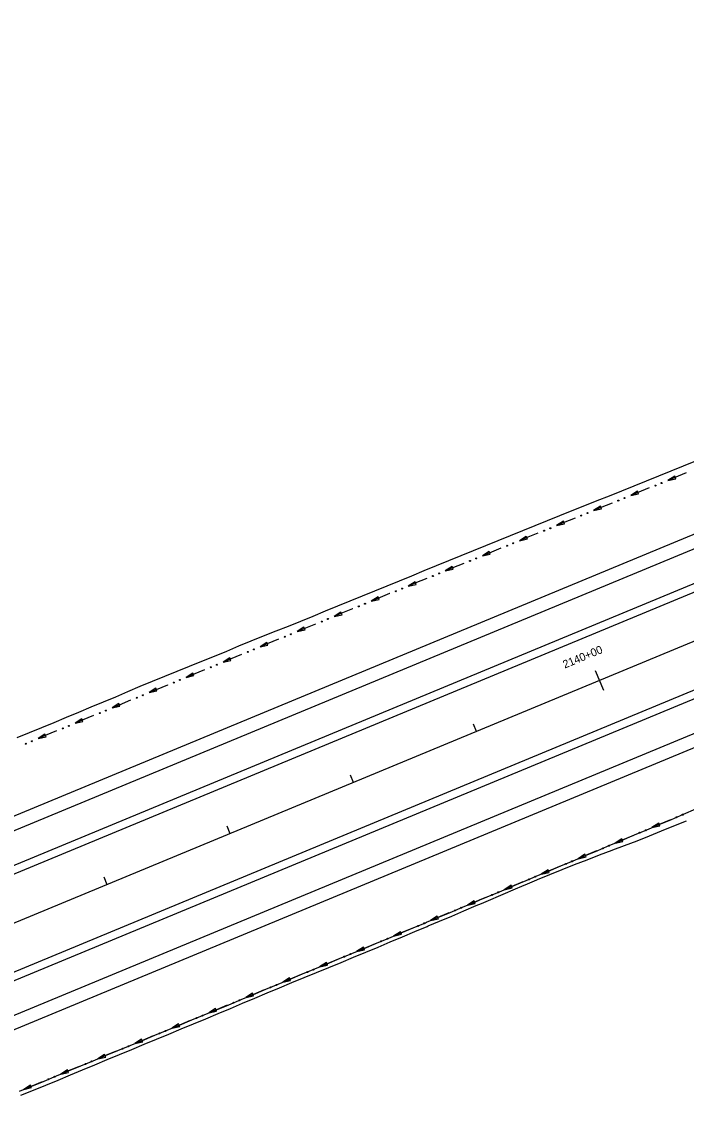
# Model space of a CAD drawing. Extents: x 1611108 to 1749517, y 619561 to 797725.
# Drawn here: x 1719500 to 1719999, y 767079 to 767893 of the extents above; entities that cross this region are included whole.
import ezdxf

# ---------------------------------------------------------------- set-up
doc = ezdxf.new("R2010")
doc.units = 0
for name, color, linetype in [('R_Ditch', 7, 'Continuous'), ('R_Horz Alg', 7, 'Continuous'), ('R_Horz Alg Stationing', 7, 'Continuous'), ('R_Proposed Const Limits', 7, 'Continuous'), ('R_Proposed Road', 7, 'Continuous')]:
    doc.layers.add(name, color=color, linetype=linetype)

msp = doc.modelspace()

# ---------------------------------------------------------------- linework, layer by layer
at = {"layer": 'R_Ditch'}
for p, q in [((1719990.05, 767551.97), (1719984.89, 767548.74)), ((1719990.85, 767550.01), (1719990.05, 767551.97)), ((1719984.89, 767548.74), (1719990.85, 767550.01)), ((1719962.21, 767540.7), (1719957.04, 767537.47)), ((1719957.04, 767537.47), (1719963, 767538.74)), ((1719963, 767538.74), (1719962.21, 767540.7)), ((1719934.37, 767529.42), (1719929.2, 767526.19)), ((1719929.2, 767526.19), (1719935.16, 767527.46)), ((1719935.16, 767527.46), (1719934.37, 767529.42)), ((1719906.53, 767518.13), (1719901.37, 767514.89)), ((1719907.33, 767516.17), (1719906.53, 767518.13)), ((1719901.37, 767514.89), (1719907.33, 767516.17)), ((1719878.7, 767506.82), (1719873.54, 767503.58)), ((1719873.54, 767503.58), (1719879.5, 767504.86)), ((1719879.5, 767504.86), (1719878.7, 767506.82)), ((1719850.88, 767495.5), (1719845.72, 767492.25)), ((1719851.68, 767493.54), (1719850.88, 767495.5)), ((1719845.72, 767492.25), (1719851.68, 767493.54)), ((1719823.07, 767484.16), (1719817.91, 767480.91)), ((1719817.91, 767480.91), (1719823.86, 767482.2)), ((1719823.86, 767482.2), (1719823.07, 767484.16)), ((1719795.26, 767472.8), (1719790.1, 767469.55)), ((1719790.1, 767469.55), (1719796.06, 767470.84)), ((1719796.06, 767470.84), (1719795.26, 767472.8)), ((1719767.45, 767461.43), (1719762.3, 767458.18)), ((1719768.25, 767459.48), (1719767.45, 767461.43)), ((1719762.3, 767458.18), (1719768.25, 767459.48)), ((1719739.65, 767450.05), (1719734.5, 767446.8)), ((1719734.5, 767446.8), (1719740.46, 767448.09)), ((1719740.46, 767448.09), (1719739.65, 767450.05)), ((1719711.86, 767438.65), (1719706.71, 767435.39)), ((1719706.71, 767435.39), (1719712.67, 767436.69)), ((1719712.67, 767436.69), (1719711.86, 767438.65)), ((1719684.08, 767427.24), (1719678.93, 767423.98)), ((1719678.93, 767423.98), (1719684.88, 767425.28)), ((1719684.88, 767425.28), (1719684.08, 767427.24)), ((1719656.3, 767415.81), (1719651.15, 767412.54)), ((1719651.15, 767412.54), (1719657.1, 767413.85)), ((1719657.1, 767413.85), (1719656.3, 767415.81)), ((1719628.52, 767404.36), (1719623.38, 767401.1)), ((1719629.33, 767402.41), (1719628.52, 767404.36)), ((1719623.38, 767401.1), (1719629.33, 767402.41)), ((1719600.76, 767392.9), (1719595.62, 767389.63)), ((1719595.62, 767389.63), (1719601.57, 767390.95)), ((1719601.57, 767390.95), (1719600.76, 767392.9)), ((1719573, 767381.43), (1719567.86, 767378.16)), ((1719573.81, 767379.47), (1719573, 767381.43)), ((1719567.86, 767378.16), (1719573.81, 767379.47)), ((1719545.24, 767369.94), (1719540.1, 767366.67)), ((1719540.1, 767366.67), (1719546.05, 767367.99)), ((1719546.05, 767367.99), (1719545.24, 767369.94)), ((1719517.49, 767358.44), (1719512.36, 767355.16)), ((1719512.36, 767355.16), (1719518.31, 767356.48)), ((1719518.31, 767356.48), (1719517.49, 767358.44)), ((1719978.09, 767291.75), (1719972.98, 767288.45)), ((1719978.91, 767289.8), (1719978.09, 767291.75)), ((1719972.98, 767288.45), (1719978.91, 767289.8)), ((1719950.41, 767280.08), (1719945.3, 767276.78)), ((1719945.3, 767276.78), (1719951.24, 767278.13)), ((1719951.24, 767278.13), (1719950.41, 767280.08)), ((1719922.73, 767268.43), (1719917.61, 767265.13)), ((1719917.61, 767265.13), (1719923.55, 767266.48)), ((1719923.55, 767266.48), (1719922.73, 767268.43)), ((1719895.04, 767256.79), (1719889.92, 767253.49)), ((1719889.92, 767253.49), (1719895.86, 767254.84)), ((1719895.86, 767254.84), (1719895.04, 767256.79)), ((1719867.34, 767245.16), (1719862.22, 767241.87)), ((1719862.22, 767241.87), (1719868.16, 767243.21)), ((1719868.16, 767243.21), (1719867.34, 767245.16)), ((1719839.64, 767233.55), (1719834.52, 767230.26)), ((1719840.46, 767231.6), (1719839.64, 767233.55)), ((1719834.52, 767230.26), (1719840.46, 767231.6)), ((1719811.93, 767221.96), (1719806.8, 767218.67)), ((1719806.8, 767218.67), (1719812.75, 767220)), ((1719812.75, 767220), (1719811.93, 767221.96)), ((1719784.22, 767210.38), (1719779.09, 767207.09)), ((1719785.03, 767208.42), (1719784.22, 767210.38)), ((1719779.09, 767207.09), (1719785.03, 767208.42)), ((1719756.5, 767198.81), (1719751.36, 767195.53)), ((1719751.36, 767195.53), (1719757.31, 767196.86)), ((1719757.31, 767196.86), (1719756.5, 767198.81)), ((1719728.77, 767187.26), (1719723.63, 767183.98)), ((1719723.63, 767183.98), (1719729.58, 767185.31)), ((1719729.58, 767185.31), (1719728.77, 767187.26)), ((1719701.03, 767175.72), (1719695.9, 767172.45)), ((1719695.9, 767172.45), (1719701.85, 767173.77)), ((1719701.85, 767173.77), (1719701.03, 767175.72)), ((1719673.29, 767164.2), (1719668.16, 767160.93)), ((1719668.16, 767160.93), (1719674.1, 767162.25)), ((1719674.1, 767162.25), (1719673.29, 767164.2)), ((1719645.55, 767152.7), (1719640.41, 767149.43)), ((1719646.36, 767150.74), (1719645.55, 767152.7)), ((1719640.41, 767149.43), (1719646.36, 767150.74)), ((1719617.79, 767141.21), (1719612.65, 767137.94)), ((1719612.65, 767137.94), (1719618.6, 767139.25)), ((1719618.6, 767139.25), (1719617.79, 767141.21)), ((1719590.03, 767129.73), (1719584.89, 767126.46)), ((1719584.89, 767126.46), (1719590.84, 767127.78)), ((1719590.84, 767127.78), (1719590.03, 767129.73)), ((1719562.27, 767118.27), (1719557.13, 767115.01)), ((1719557.13, 767115.01), (1719563.08, 767116.32)), ((1719563.08, 767116.32), (1719562.27, 767118.27)), ((1719534.5, 767106.83), (1719529.35, 767103.56)), ((1719529.35, 767103.56), (1719535.3, 767104.87)), ((1719535.3, 767104.87), (1719534.5, 767106.83)), ((1719506.72, 767095.4), (1719501.57, 767092.14)), ((1719507.52, 767093.44), (1719506.72, 767095.4)), ((1719501.57, 767092.14), (1719507.52, 767093.44))]:
    msp.add_line(p, q, dxfattribs=at)
for points in [[(1719998.8, 767554.36), (1719989.73, 767550.69), (1719984.89, 767548.74)], [(1719970.95, 767543.1), (1719961.91, 767539.44), (1719957.04, 767537.47)], [(1719970.98, 767543.11), (1719970.95, 767543.1)], [(1719943.11, 767531.82), (1719934.11, 767528.18), (1719929.2, 767526.19)], [(1719943.14, 767531.84), (1719943.11, 767531.82)], [(1719915.27, 767520.54), (1719906.31, 767516.9), (1719901.37, 767514.89)], [(1719915.3, 767520.55), (1719915.27, 767520.54)], [(1719887.44, 767509.23), (1719878.52, 767505.6), (1719873.54, 767503.58)], [(1719887.47, 767509.25), (1719887.44, 767509.23)], [(1719859.62, 767497.91), (1719850.73, 767494.29), (1719845.72, 767492.25)], [(1719859.65, 767497.93), (1719859.62, 767497.91)], [(1719831.8, 767486.58), (1719822.95, 767482.97), (1719817.91, 767480.91)], [(1719831.83, 767486.59), (1719831.8, 767486.58)], [(1719803.99, 767475.23), (1719795.17, 767471.63), (1719790.1, 767469.55)], [(1719804.02, 767475.24), (1719803.99, 767475.23)], [(1719776.18, 767463.86), (1719767.41, 767460.27), (1719762.3, 767458.18)], [(1719776.22, 767463.88), (1719776.18, 767463.86)], [(1719748.38, 767452.48), (1719739.64, 767448.9), (1719734.5, 767446.8)], [(1719748.42, 767452.5), (1719748.38, 767452.48)], [(1719720.59, 767441.09), (1719711.89, 767437.52), (1719706.71, 767435.39)], [(1719720.63, 767441.1), (1719720.59, 767441.09)], [(1719692.8, 767429.68), (1719684.14, 767426.12), (1719678.93, 767423.98)], [(1719692.84, 767429.69), (1719692.8, 767429.68)], [(1719665.02, 767418.25), (1719656.39, 767414.7), (1719651.15, 767412.54)], [(1719665.06, 767418.27), (1719665.02, 767418.26)], [(1719637.25, 767406.82), (1719628.66, 767403.27), (1719623.38, 767401.1)], [(1719637.28, 767406.83), (1719637.25, 767406.82)], [(1719609.48, 767395.36), (1719600.93, 767391.83), (1719595.62, 767389.63)], [(1719609.52, 767395.38), (1719609.48, 767395.36)], [(1719581.72, 767383.89), (1719573.2, 767380.37), (1719567.86, 767378.16)], [(1719581.75, 767383.91), (1719581.72, 767383.89)], [(1719553.96, 767372.41), (1719545.48, 767368.89), (1719540.1, 767366.67)], [(1719554, 767372.42), (1719553.96, 767372.41)], [(1719526.21, 767360.91), (1719517.77, 767357.4), (1719512.36, 767355.16)], [(1719526.25, 767360.92), (1719526.21, 767360.91)], [(1719498.31, 767090.8), (1719507.56, 767094.6), (1719516.81, 767098.4), (1719526.06, 767102.21), (1719535.3, 767106.02), (1719544.55, 767109.82), (1719553.8, 767113.64), (1719563.04, 767117.45), (1719572.29, 767121.26), (1719581.53, 767125.08), (1719590.77, 767128.89), (1719600.02, 767132.71), (1719609.26, 767136.53), (1719618.5, 767140.35), (1719627.74, 767144.18), (1719636.98, 767148), (1719646.22, 767151.83), (1719655.45, 767155.66), (1719664.69, 767159.49), (1719673.93, 767163.32), (1719683.16, 767167.16), (1719692.4, 767170.99), (1719701.63, 767174.83), (1719710.87, 767178.67), (1719720.1, 767182.51), (1719729.33, 767186.35), (1719738.56, 767190.19), (1719747.79, 767194.04), (1719757.03, 767197.89), (1719766.26, 767201.73), (1719775.48, 767205.58), (1719784.71, 767209.44), (1719793.94, 767213.29), (1719803.17, 767217.15), (1719803.9, 767217.45), (1719812.39, 767221), (1719821.62, 767224.86), (1719830.84, 767228.72), (1719840.07, 767232.58), (1719843.87, 767234.18), (1719843.95, 767234.21), (1719849.29, 767236.45), (1719858.52, 767240.31), (1719862.08, 767241.81), (1719867.74, 767244.18), (1719876.14, 767247.7), (1719876.96, 767248.05), (1719885.63, 767251.69), (1719886.18, 767251.92), (1719895.4, 767255.79), (1719904.62, 767259.67), (1719913.84, 767263.54), (1719923.05, 767267.42), (1719932.27, 767271.3), (1719941.49, 767275.18), (1719942.18, 767275.47), (1719950.71, 767279.06), (1719959.92, 767282.94), (1719969.14, 767286.83), (1719978.35, 767290.71), (1719987.56, 767294.6), (1719996.78, 767298.49), (1720005.99, 767302.39)], [(1719986.8, 767294.28), (1719978.35, 767290.71), (1719972.98, 767288.45)], [(1719986.83, 767294.29), (1719986.8, 767294.28)], [(1719959.12, 767282.6), (1719950.71, 767279.06), (1719945.3, 767276.78)], [(1719959.15, 767282.62), (1719959.12, 767282.6)], [(1719931.44, 767270.94), (1719923.05, 767267.42), (1719917.61, 767265.13)], [(1719931.47, 767270.96), (1719931.44, 767270.94)], [(1719903.75, 767259.3), (1719895.4, 767255.79), (1719889.92, 767253.49)], [(1719903.78, 767259.31), (1719903.75, 767259.3)], [(1719876.05, 767247.67), (1719867.74, 767244.18), (1719862.22, 767241.87)], [(1719876.09, 767247.68), (1719876.05, 767247.67)], [(1719848.35, 767236.05), (1719843.95, 767234.21), (1719843.87, 767234.18), (1719840.07, 767232.58), (1719834.52, 767230.26)], [(1719848.39, 767236.07), (1719848.35, 767236.05)], [(1719820.64, 767224.45), (1719812.39, 767221), (1719806.8, 767218.67)], [(1719820.68, 767224.47), (1719820.64, 767224.45)], [(1719792.93, 767212.87), (1719784.71, 767209.44), (1719779.09, 767207.09)], [(1719792.96, 767212.88), (1719792.93, 767212.87)], [(1719765.21, 767201.3), (1719757.03, 767197.89), (1719751.36, 767195.53)], [(1719765.24, 767201.31), (1719765.21, 767201.3)], [(1719737.48, 767189.74), (1719729.33, 767186.35), (1719723.63, 767183.98)], [(1719737.52, 767189.76), (1719737.48, 767189.74)], [(1719709.75, 767178.2), (1719701.63, 767174.83), (1719695.9, 767172.45)], [(1719709.78, 767178.22), (1719709.75, 767178.2)], [(1719682.01, 767166.68), (1719673.93, 767163.32), (1719668.16, 767160.93)], [(1719682.05, 767166.69), (1719682.01, 767166.68)], [(1719654.27, 767155.17), (1719646.22, 767151.83), (1719640.41, 767149.43)], [(1719654.3, 767155.18), (1719654.27, 767155.17)], [(1719626.51, 767143.67), (1719618.5, 767140.35), (1719612.65, 767137.94)], [(1719626.55, 767143.69), (1719626.51, 767143.67)], [(1719598.76, 767132.19), (1719590.77, 767128.89), (1719584.89, 767126.46)], [(1719598.79, 767132.21), (1719598.76, 767132.19)], [(1719570.99, 767120.73), (1719563.04, 767117.45), (1719557.13, 767115.01)], [(1719571.03, 767120.74), (1719570.99, 767120.73)], [(1719543.22, 767109.28), (1719535.3, 767106.02), (1719529.35, 767103.56)], [(1719543.26, 767109.29), (1719543.22, 767109.28)], [(1719515.45, 767097.84), (1719507.56, 767094.6), (1719501.57, 767092.14)], [(1719515.48, 767097.86), (1719515.45, 767097.84)]]:
    msp.add_lwpolyline(points, dxfattribs=at)
for centre in [(1719975.62, 767544.95), (1719980.26, 767546.83), (1719952.42, 767535.56), (1719947.77, 767533.68), (1719919.94, 767522.39), (1719924.58, 767524.27), (1719892.11, 767511.09), (1719896.75, 767512.97), (1719868.92, 767501.66), (1719864.28, 767499.77), (1719836.46, 767488.44), (1719841.1, 767490.33), (1719808.65, 767477.09), (1719813.29, 767478.99), (1719780.84, 767465.73), (1719785.48, 767467.63), (1719753.04, 767454.35), (1719757.68, 767456.25), (1719729.89, 767444.86), (1719725.25, 767442.96), (1719697.46, 767431.55), (1719702.1, 767433.46), (1719669.68, 767420.13), (1719674.31, 767422.04), (1719641.91, 767408.7), (1719646.54, 767410.6), (1719614.14, 767397.24), (1719618.77, 767399.16), (1719591, 767387.69), (1719586.37, 767385.78), (1719558.62, 767374.29), (1719563.25, 767376.21), (1719535.49, 767364.72), (1719530.87, 767362.8), (1719503.12, 767351.28), (1719507.75, 767353.21), (1719996.05, 767298.15), (1719991.44, 767296.2), (1719963.76, 767284.52), (1719968.38, 767286.47), (1719940.7, 767274.8), (1719936.08, 767272.86), (1719908.39, 767261.21), (1719913.01, 767263.15), (1719880.7, 767249.58), (1719885.32, 767251.52), (1719853, 767237.96), (1719857.62, 767239.9), (1719825.29, 767226.36), (1719829.91, 767228.29), (1719802.2, 767216.7), (1719797.58, 767214.77), (1719769.86, 767203.2), (1719774.48, 767205.13), (1719746.76, 767193.57), (1719742.13, 767191.64), (1719714.4, 767180.1), (1719719.03, 767182.02), (1719686.66, 767168.57), (1719691.29, 767170.49), (1719658.92, 767157.06), (1719663.55, 767158.98), (1719631.17, 767145.56), (1719635.8, 767147.48), (1719608.04, 767135.99), (1719603.41, 767134.08), (1719575.65, 767122.61), (1719580.28, 767124.52), (1719547.88, 767111.16), (1719552.51, 767113.07), (1719520.1, 767099.72), (1719524.74, 767101.63)]:
    msp.add_circle(centre, 0.375, dxfattribs=at)
at = {"layer": 'R_Horz Alg'}
msp.add_line((1715964.86, 765755.05), (1723860.62, 769025.58), dxfattribs=at)
at = {"layer": 'R_Horz Alg Stationing'}
for points in [[(1719930.46, 767406.32), (1719936.59, 767391.54)], [(1719838.84, 767366.2), (1719841.14, 767360.66)], [(1719746.45, 767327.93), (1719748.75, 767322.39)], [(1719654.07, 767289.67), (1719656.36, 767284.12)], [(1719561.68, 767251.4), (1719563.97, 767245.85)]]:
    msp.add_lwpolyline(points, dxfattribs=at)
at = {"layer": 'R_Proposed Const Limits'}
for points in [[(1719496.7, 767356.01), (1719505.95, 767359.8), (1719515.25, 767363.49), (1719524.49, 767367.3), (1719533.7, 767371.21), (1719542.9, 767375.12), (1719552.14, 767378.94), (1719561.39, 767382.74), (1719570.63, 767386.58), (1719579.82, 767390.52), (1719589.02, 767394.44), (1719598.26, 767398.26), (1719607.52, 767402.03), (1719616.79, 767405.78), (1719626.07, 767409.52), (1719635.34, 767413.26), (1719644.62, 767417), (1719653.88, 767420.77), (1719663.11, 767424.62), (1719672.35, 767428.44), (1719681.62, 767432.2), (1719690.89, 767435.95), (1719700.22, 767439.54), (1719709.49, 767443.31), (1719718.75, 767447.09), (1719728.01, 767450.86), (1719737.26, 767454.66), (1719746.51, 767458.46), (1719755.76, 767462.26), (1719765.02, 767466.03), (1719774.28, 767469.81), (1719783.54, 767473.58), (1719792.8, 767477.35), (1719802.06, 767481.12), (1719811.33, 767484.89), (1719820.59, 767488.66), (1719829.85, 767492.43), (1719839.12, 767496.19), (1719848.39, 767499.95), (1719857.65, 767503.72), (1719866.91, 767507.49), (1719876.19, 767511.22), (1719885.45, 767515), (1719894.71, 767518.78), (1719903.98, 767522.53), (1719913.25, 767526.27), (1719922.55, 767529.95), (1719931.86, 767533.6), (1719941.17, 767537.26), (1719950.48, 767540.93), (1719959.73, 767544.71), (1719968.99, 767548.49), (1719978.25, 767552.27), (1719987.51, 767556.04), (1719996.78, 767559.8), (1720006.04, 767563.56)], [(1719499.51, 767087.91), (1719508.8, 767091.61), (1719518.09, 767095.32), (1719527.33, 767099.15), (1719536.56, 767102.99), (1719545.79, 767106.84), (1719555.03, 767110.66), (1719564.27, 767114.48), (1719573.51, 767118.31), (1719582.75, 767122.13), (1719591.99, 767125.96), (1719601.23, 767129.79), (1719610.46, 767133.62), (1719619.7, 767137.45), (1719628.93, 767141.29), (1719638.16, 767145.14), (1719647.39, 767148.99), (1719656.62, 767152.84), (1719665.84, 767156.7), (1719675.07, 767160.57), (1719684.29, 767164.44), (1719693.51, 767168.3), (1719702.73, 767172.17), (1719711.98, 767175.98), (1719721.23, 767179.79), (1719730.48, 767183.59), (1719739.72, 767187.4), (1719748.97, 767191.21), (1719758.2, 767195.05), (1719767.43, 767198.89), (1719776.67, 767202.74), (1719785.89, 767206.61), (1719795.08, 767210.53), (1719804.32, 767214.37), (1719805.05, 767214.67), (1719813.55, 767218.2), (1719822.75, 767222.13), (1719831.95, 767226.06), (1719841.18, 767229.9), (1719844.98, 767231.48), (1719845.07, 767231.52), (1719850.41, 767233.75), (1719859.61, 767237.68), (1719863.15, 767239.23), (1719868.77, 767241.7), (1719877.14, 767245.3), (1719877.96, 767245.64), (1719886.65, 767249.24), (1719887.2, 767249.46), (1719896.44, 767253.28), (1719905.71, 767257.04), (1719914.99, 767260.75), (1719924.32, 767264.36), (1719933.67, 767267.91), (1719943.04, 767271.42), (1719943.75, 767271.69), (1719952.42, 767274.92), (1719961.81, 767278.39), (1719971.07, 767282.17), (1719980.29, 767286.03), (1719989.54, 767289.84), (1719998.88, 767293.41)]]:
    msp.add_lwpolyline(points, dxfattribs=at)
at = {"layer": 'R_Proposed Road'}
for p, q in [((1715936.54, 765823.42), (1723832.3, 769093.95)), ((1715940.37, 765814.18), (1723836.12, 769084.71)), ((1715949.55, 765792.01), (1723845.31, 769062.54)), ((1715951.85, 765786.47), (1723847.6, 769056.99)), ((1715977.87, 765723.64), (1723873.63, 768994.17)), ((1715980.17, 765718.1), (1723875.92, 768988.63)), ((1715989.35, 765695.93), (1723885.11, 768966.45)), ((1715993.18, 765686.69), (1723888.93, 768957.22))]:
    msp.add_line(p, q, dxfattribs=at)

# ---------------------------------------------------------------- texts
at = {"layer": 'R_Horz Alg Stationing'}
msp.add_text('2140+00', height=6, rotation=22.5, dxfattribs=at).set_placement((1719907.56, 767407.66))

doc.saveas('drawing.dxf')
